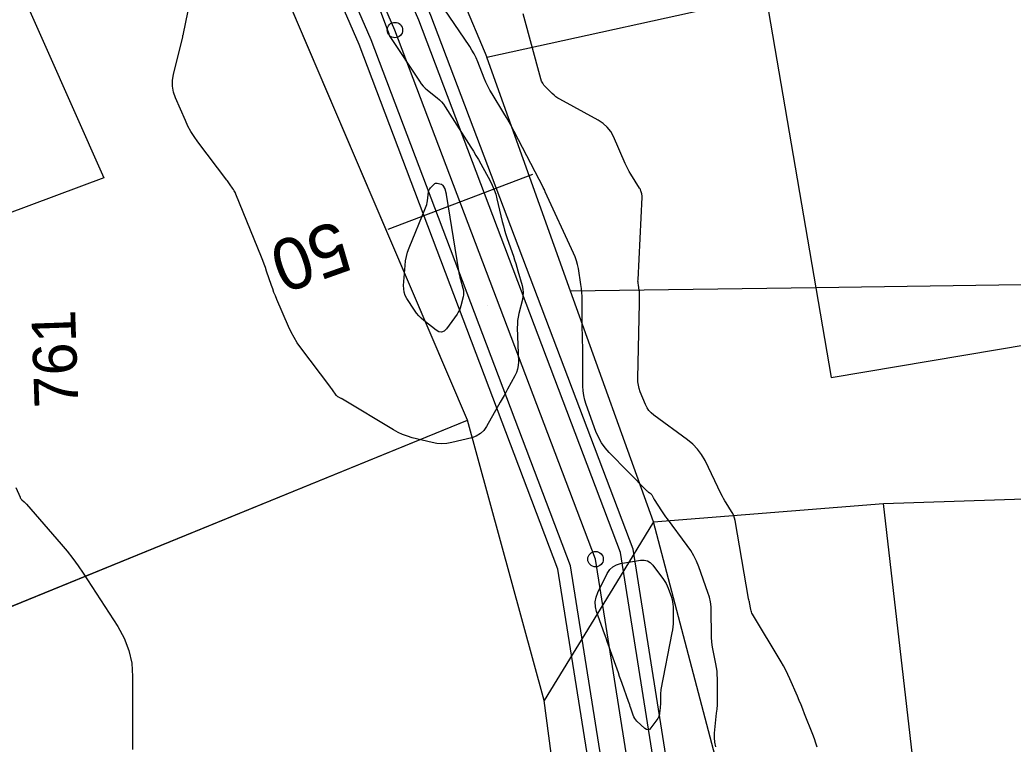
# Model space of a CAD drawing. Extents: x -534481 to -534262, y -1190577 to -1190138.
# Drawn here: x -534403.93 to -534384.66, y -1190491.61 to -1190477.55 of the extents above; entities that cross this region are included whole.
import ezdxf

# ---------------------------------------------------------------- set-up
doc = ezdxf.new("R2010")
doc.units = 0
for name, color, linetype in [('Bonity', 7, 'Continuous'), ('Definiční body', 7, 'Continuous'), ('Polygon budovy', 7, 'Continuous'), ('Polygon parcely', 7, 'Continuous'), ('Vrstva 18', 7, 'Continuous'), ('Vrstva 19', 7, 'Continuous'), ('Vrstva 31', 7, 'Continuous'), ('Vrstva 35', 7, 'Continuous'), ('Vrstva 37', 7, 'Continuous')]:
    doc.layers.add(name, color=color, linetype=linetype)

msp = doc.modelspace()

# ---------------------------------------------------------------- linework, layer by layer
at = {"layer": 'Bonity'}
msp.add_lwpolyline([(-534408.105, -1190518.46), (-534393.616, -1190502.389), (-534391.346, -1190496.962), (-534392.763, -1190488.017), (-534396.655, -1190477.752), (-534402.513, -1190464.283), (-534404.757, -1190456.741), (-534408.311, -1190433.088), (-534409.248, -1190427.879), (-534409.316, -1190416.054), (-534409.076, -1190409.418), (-534409.868, -1190391.439)], dxfattribs=at)
at = {"layer": 'Definiční body'}
for p, q in [((-534397.97, -1190470.9), (-534394.87, -1190478.28)), ((-534395.25, -1190485.32), (-534400.89, -1190472.11)), ((-534394.77, -1190478.57), (-534394.87, -1190478.28)), ((-534393.25, -1190482.82), (-534394.77, -1190478.57)), ((-534391.64, -1190487.29), (-534393.25, -1190482.82)), ((-534408.72, -1190490.82), (-534395.25, -1190485.32)), ((-534393.76, -1190490.76), (-534395.25, -1190485.32)), ((-534391.64, -1190487.29), (-534387.18, -1190486.94))]:
    msp.add_line(p, q, dxfattribs=at)
for points in [[(-534394.87, -1190478.28), (-534389.45, -1190477.08), (-534382.56, -1190476.12), (-534376.75, -1190475.31)], [(-534377.4, -1190482.59), (-534388.49, -1190482.75), (-534393.25, -1190482.82)], [(-534387.18, -1190486.94), (-534381.11, -1190486.74), (-534380.38, -1190486.72), (-534376.48, -1190486.28)], [(-534385.13, -1190504.81), (-534385.97, -1190497.46), (-534387.18, -1190486.94)], [(-534391.64, -1190487.29), (-534392.36, -1190488.47), (-534393.76, -1190490.76)], [(-534389.82, -1190497.69), (-534389.73, -1190494.54), (-534391.64, -1190487.29)], [(-534393.4, -1190496.16), (-534393.44, -1190493.16), (-534393.76, -1190490.76)]]:
    msp.add_lwpolyline(points, dxfattribs=at)
at = {"layer": 'Polygon parcely'}
for points in [[(-534413.98, -1190478.05), (-534410.74, -1190485.76), (-534408.96, -1190490.21), (-534408.72, -1190490.82), (-534395.25, -1190485.32), (-534400.89, -1190472.11), (-534405.17, -1190474.16), (-534402.3, -1190480.62), (-534406.62, -1190482.23), (-534409.2, -1190476.06), (-534410.27, -1190476.57)], [(-534389.45, -1190477.08), (-534389.41, -1190477.39), (-534388.49, -1190482.75), (-534388.19, -1190484.49), (-534381.78, -1190483.41), (-534381.11, -1190486.74), (-534380.38, -1190486.72), (-534376.48, -1190486.28), (-534376.96, -1190484.36), (-534377.4, -1190482.59), (-534375.83, -1190482.13), (-534376.75, -1190475.31), (-534382.56, -1190476.12)]]:
    msp.add_lwpolyline(points, close=True, dxfattribs=at)
at = {"layer": 'Vrstva 18'}
for points in [[(-534397.096, -1190476.95), (-534396.777, -1190477.804), (-534396.774, -1190477.81), (-534396.773, -1190477.816), (-534396.771, -1190477.821), (-534396.77, -1190477.828), (-534396.765, -1190477.852), (-534396.763, -1190477.858), (-534396.761, -1190477.863), (-534396.759, -1190477.869), (-534396.756, -1190477.874), (-534396.178, -1190478.746), (-534396.144, -1190478.794), (-534396.106, -1190478.838), (-534396.065, -1190478.88), (-534396.021, -1190478.918), (-534395.836, -1190479.065), (-534395.791, -1190479.104), (-534395.75, -1190479.145), (-534395.713, -1190479.19), (-534395.68, -1190479.239), (-534395.181, -1190480.022), (-534395.132, -1190480.102), (-534395.083, -1190480.183), (-534395.036, -1190480.265), (-534394.99, -1190480.347), (-534394.809, -1190480.679), (-534394.767, -1190480.763), (-534394.73, -1190480.849), (-534394.7, -1190480.938), (-534394.675, -1190481.028), (-534394.572, -1190481.469), (-534394.552, -1190481.552), (-534394.529, -1190481.634), (-534394.504, -1190481.715), (-534394.477, -1190481.796), (-534394.357, -1190482.14), (-534394.333, -1190482.21), (-534394.311, -1190482.28), (-534394.289, -1190482.35), (-534394.269, -1190482.42), (-534394.187, -1190482.71), (-534394.173, -1190482.777), (-534394.167, -1190482.845), (-534394.171, -1190482.912), (-534394.183, -1190482.98), (-534394.251, -1190483.251), (-534394.266, -1190483.319), (-534394.275, -1190483.387), (-534394.28, -1190483.456), (-534394.281, -1190483.526), (-534394.259, -1190484.187), (-534394.262, -1190484.259), (-534394.274, -1190484.328), (-534394.295, -1190484.396), (-534394.326, -1190484.461), (-534394.468, -1190484.717), (-534394.503, -1190484.781), (-534394.539, -1190484.844), (-534394.575, -1190484.908), (-534394.611, -1190484.972), (-534394.876, -1190485.441), (-534394.931, -1190485.52), (-534394.998, -1190485.582), (-534395.076, -1190485.63), (-534395.166, -1190485.661), (-534395.551, -1190485.756), (-534395.647, -1190485.774), (-534395.743, -1190485.78), (-534395.839, -1190485.774), (-534395.935, -1190485.756), (-534396.319, -1190485.66), (-534396.414, -1190485.633), (-534396.506, -1190485.599), (-534396.594, -1190485.558), (-534396.681, -1190485.51), (-534397.67, -1190484.912), (-534397.677, -1190484.908), (-534397.684, -1190484.904), (-534397.691, -1190484.901), (-534397.699, -1190484.897), (-534397.738, -1190484.88), (-534397.746, -1190484.876), (-534397.759, -1190484.869), (-534397.764, -1190484.865), (-534397.769, -1190484.862), (-534397.784, -1190484.85), (-534397.787, -1190484.847), (-534397.789, -1190484.844), (-534397.792, -1190484.841), (-534397.795, -1190484.838), (-534397.866, -1190484.734), (-534397.878, -1190484.715), (-534397.891, -1190484.697), (-534397.905, -1190484.679), (-534397.918, -1190484.661), (-534398.48, -1190483.918), (-534398.549, -1190483.82), (-534398.612, -1190483.719), (-534398.669, -1190483.614), (-534398.72, -1190483.506), (-534398.946, -1190482.979), (-534398.974, -1190482.911), (-534399.001, -1190482.843), (-534399.026, -1190482.775), (-534399.05, -1190482.706), (-534399.143, -1190482.429), (-534399.167, -1190482.36), (-534399.191, -1190482.291), (-534399.217, -1190482.223), (-534399.244, -1190482.155), (-534399.738, -1190480.933), (-534399.741, -1190480.927), (-534399.744, -1190480.921), (-534399.747, -1190480.915), (-534399.75, -1190480.909), (-534399.774, -1190480.87), (-534399.787, -1190480.848), (-534399.794, -1190480.838), (-534399.865, -1190480.734), (-534399.878, -1190480.716), (-534399.89, -1190480.698), (-534399.904, -1190480.68), (-534399.917, -1190480.662), (-534400.48, -1190479.918), (-534400.549, -1190479.82), (-534400.612, -1190479.719), (-534400.669, -1190479.614), (-534400.72, -1190479.506), (-534400.909, -1190479.065), (-534400.947, -1190478.954), (-534400.966, -1190478.841), (-534400.966, -1190478.727), (-534400.947, -1190478.611), (-534400.771, -1190477.88), (-534400.769, -1190477.87), (-534400.766, -1190477.86), (-534400.76, -1190477.841), (-534400.757, -1190477.831), (-534400.755, -1190477.821), (-534400.589, -1190476.994)], [(-534388.464, -1190491.668), (-534388.488, -1190491.585), (-534388.515, -1190491.502), (-534388.546, -1190491.421), (-534388.708, -1190491.015), (-534388.742, -1190490.93), (-534388.777, -1190490.845), (-534388.813, -1190490.76), (-534388.849, -1190490.675), (-534388.994, -1190490.337), (-534389.031, -1190490.253), (-534389.072, -1190490.17), (-534389.115, -1190490.089), (-534389.161, -1190490.01), (-534389.717, -1190489.087), (-534389.729, -1190489.065), (-534389.739, -1190489.042), (-534389.746, -1190489.018), (-534389.751, -1190488.994), (-534389.774, -1190488.858), (-534389.776, -1190488.851), (-534389.777, -1190488.845), (-534389.779, -1190488.838), (-534389.781, -1190488.831), (-534389.791, -1190488.805), (-534389.793, -1190488.799), (-534389.795, -1190488.792), (-534389.796, -1190488.786), (-534389.798, -1190488.779), (-534390.054, -1190487.268), (-534390.065, -1190487.221), (-534390.08, -1190487.176), (-534390.1, -1190487.132), (-534390.124, -1190487.09), (-534390.23, -1190486.926), (-534390.256, -1190486.885), (-534390.281, -1190486.843), (-534390.304, -1190486.8), (-534390.326, -1190486.757), (-534390.64, -1190486.106), (-534390.706, -1190485.989), (-534390.784, -1190485.882), (-534390.876, -1190485.785), (-534390.98, -1190485.699), (-534391.634, -1190485.223), (-534391.685, -1190485.18), (-534391.728, -1190485.132), (-534391.765, -1190485.078), (-534391.794, -1190485.018), (-534391.895, -1190484.768), (-534391.917, -1190484.704), (-534391.932, -1190484.64), (-534391.94, -1190484.574), (-534391.942, -1190484.507), (-534391.91, -1190483.052), (-534391.909, -1190483.031), (-534391.909, -1190483.01), (-534391.909, -1190482.99), (-534391.909, -1190482.969), (-534391.909, -1190482.886), (-534391.909, -1190482.865), (-534391.911, -1190482.845), (-534391.913, -1190482.824), (-534391.916, -1190482.804), (-534391.933, -1190482.696), (-534391.937, -1190482.671), (-534391.939, -1190482.646), (-534391.94, -1190482.621), (-534391.939, -1190482.596), (-534391.861, -1190480.991), (-534391.861, -1190480.976), (-534391.862, -1190480.961), (-534391.864, -1190480.947), (-534391.868, -1190480.932), (-534391.884, -1190480.874), (-534391.889, -1190480.859), (-534391.894, -1190480.845), (-534391.901, -1190480.832), (-534391.908, -1190480.819), (-534392.079, -1190480.546), (-534392.109, -1190480.496), (-534392.137, -1190480.445), (-534392.164, -1190480.392), (-534392.188, -1190480.339), (-534392.417, -1190479.82), (-534392.47, -1190479.722), (-534392.536, -1190479.636), (-534392.616, -1190479.562), (-534392.71, -1190479.501), (-534393.456, -1190479.094), (-534393.496, -1190479.071), (-534393.534, -1190479.045), (-534393.569, -1190479.016), (-534393.603, -1190478.985), (-534393.734, -1190478.854), (-534393.764, -1190478.82), (-534393.789, -1190478.783), (-534393.809, -1190478.743), (-534393.823, -1190478.7), (-534394.17, -1190477.437)]]:
    msp.add_lwpolyline(points, dxfattribs=at)
msp.add_lwpolyline([(-534391.717, -1190491.319), (-534391.746, -1190491.331), (-534391.777, -1190491.325), (-534391.81, -1190491.302), (-534391.96, -1190491.161), (-534391.984, -1190491.135), (-534392.004, -1190491.108), (-534392.02, -1190491.078), (-534392.033, -1190491.045), (-534392.078, -1190490.911), (-534392.089, -1190490.878), (-534392.1, -1190490.845), (-534392.112, -1190490.811), (-534392.123, -1190490.778), (-534392.247, -1190490.43), (-534392.271, -1190490.361), (-534392.296, -1190490.292), (-534392.32, -1190490.223), (-534392.345, -1190490.154), (-534392.472, -1190489.797), (-534392.502, -1190489.715), (-534392.531, -1190489.633), (-534392.56, -1190489.55), (-534392.589, -1190489.467), (-534392.742, -1190489.032), (-534392.765, -1190488.939), (-534392.769, -1190488.847), (-534392.754, -1190488.756), (-534392.719, -1190488.666), (-534392.536, -1190488.294), (-534392.489, -1190488.221), (-534392.431, -1190488.165), (-534392.36, -1190488.126), (-534392.277, -1190488.103), (-534391.889, -1190488.038), (-534391.82, -1190488.035), (-534391.757, -1190488.05), (-534391.702, -1190488.082), (-534391.654, -1190488.133), (-534391.444, -1190488.413), (-534391.417, -1190488.451), (-534391.393, -1190488.492), (-534391.373, -1190488.534), (-534391.355, -1190488.577), (-534391.292, -1190488.755), (-534391.278, -1190488.8), (-534391.268, -1190488.846), (-534391.262, -1190488.892), (-534391.26, -1190488.939), (-534391.259, -1190489.208), (-534391.26, -1190489.269), (-534391.264, -1190489.329), (-534391.271, -1190489.389), (-534391.281, -1190489.449), (-534391.494, -1190490.548), (-534391.499, -1190490.577), (-534391.502, -1190490.607), (-534391.504, -1190490.636), (-534391.505, -1190490.666), (-534391.504, -1190490.79), (-534391.504, -1190490.817), (-534391.505, -1190490.844), (-534391.507, -1190490.872), (-534391.509, -1190490.899), (-534391.521, -1190491.007), (-534391.525, -1190491.034), (-534391.533, -1190491.059), (-534391.544, -1190491.083), (-534391.558, -1190491.106), (-534391.69, -1190491.29)], close=True, dxfattribs=at)
at = {"layer": 'Vrstva 19'}
for points in [[(-534390.433, -1190491.658), (-534390.451, -1190491.57), (-534390.457, -1190491.482), (-534390.453, -1190491.391), (-534390.414, -1190491.008), (-534390.406, -1190490.926), (-534390.401, -1190490.844), (-534390.398, -1190490.762), (-534390.398, -1190490.68), (-534390.4, -1190490.333), (-534390.402, -1190490.26), (-534390.407, -1190490.188), (-534390.417, -1190490.116), (-534390.429, -1190490.045), (-534390.487, -1190489.759), (-534390.499, -1190489.688), (-534390.508, -1190489.616), (-534390.514, -1190489.544), (-534390.516, -1190489.471), (-534390.518, -1190489.038), (-534390.522, -1190488.942), (-534390.534, -1190488.847), (-534390.555, -1190488.754), (-534390.583, -1190488.663), (-534390.76, -1190488.167), (-534390.804, -1190488.057), (-534390.856, -1190487.95), (-534390.916, -1190487.848), (-534390.984, -1190487.75), (-534391.37, -1190487.236), (-534391.398, -1190487.198), (-534391.426, -1190487.16), (-534391.452, -1190487.121), (-534391.478, -1190487.082), (-534391.621, -1190486.862), (-534391.626, -1190486.853), (-534391.632, -1190486.844), (-534391.636, -1190486.835), (-534391.641, -1190486.826), (-534391.659, -1190486.788), (-534391.664, -1190486.779), (-534391.67, -1190486.771), (-534391.677, -1190486.764), (-534391.685, -1190486.757), (-534391.724, -1190486.729), (-534391.734, -1190486.722), (-534391.742, -1190486.714), (-534391.751, -1190486.707), (-534391.759, -1190486.699), (-534392.498, -1190485.948), (-534392.579, -1190485.857), (-534392.649, -1190485.758), (-534392.708, -1190485.653), (-534392.755, -1190485.54), (-534392.946, -1190485.017), (-534392.973, -1190484.93), (-534392.993, -1190484.842), (-534393.005, -1190484.752), (-534393.009, -1190484.661), (-534393.009, -1190484.246), (-534393.009, -1190484.178), (-534393.009, -1190484.11), (-534393.01, -1190484.042), (-534393.011, -1190483.974), (-534393.017, -1190483.703), (-534393.019, -1190483.635), (-534393.02, -1190483.567), (-534393.02, -1190483.499), (-534393.02, -1190483.432), (-534393.02, -1190483.002), (-534393.022, -1190482.923), (-534393.027, -1190482.845), (-534393.034, -1190482.767), (-534393.046, -1190482.689), (-534393.097, -1190482.379), (-534393.112, -1190482.302), (-534393.133, -1190482.227), (-534393.158, -1190482.153), (-534393.188, -1190482.081), (-534393.739, -1190480.892), (-534393.743, -1190480.882), (-534393.746, -1190480.873), (-534393.753, -1190480.852), (-534393.756, -1190480.845), (-534393.759, -1190480.838), (-534393.77, -1190480.818), (-534393.773, -1190480.811), (-534394.342, -1190479.717), (-534394.389, -1190479.627), (-534394.438, -1190479.538), (-534394.489, -1190479.45), (-534394.541, -1190479.363), (-534394.77, -1190478.99), (-534394.813, -1190478.916), (-534394.853, -1190478.841), (-534394.889, -1190478.765), (-534394.922, -1190478.686), (-534395.047, -1190478.37), (-534395.081, -1190478.292), (-534395.118, -1190478.216), (-534395.16, -1190478.142), (-534395.205, -1190478.07), (-534395.7, -1190477.339)], [(-534404.007, -1190486.624), (-534403.927, -1190486.816), (-534403.921, -1190486.83), (-534403.913, -1190486.842), (-534403.904, -1190486.854), (-534403.893, -1190486.865), (-534403.847, -1190486.905), (-534403.835, -1190486.915), (-534403.824, -1190486.926), (-534403.814, -1190486.937), (-534403.803, -1190486.948), (-534403.126, -1190487.727), (-534403.012, -1190487.863), (-534402.903, -1190488.002), (-534402.799, -1190488.145), (-534402.7, -1190488.292), (-534402.031, -1190489.324), (-534401.905, -1190489.551), (-534401.815, -1190489.788), (-534401.761, -1190490.036), (-534401.743, -1190490.295), (-534401.743, -1190491.711)]]:
    msp.add_lwpolyline(points, dxfattribs=at)
msp.add_lwpolyline([(-534395.702, -1190483.595), (-534395.75, -1190483.615), (-534395.802, -1190483.609), (-534395.857, -1190483.576), (-534396.094, -1190483.386), (-534396.145, -1190483.342), (-534396.192, -1190483.294), (-534396.235, -1190483.242), (-534396.274, -1190483.187), (-534396.421, -1190482.959), (-534396.453, -1190482.9), (-534396.474, -1190482.839), (-534396.485, -1190482.775), (-534396.486, -1190482.709), (-534396.459, -1190482.317), (-534396.45, -1190482.229), (-534396.433, -1190482.144), (-534396.41, -1190482.06), (-534396.38, -1190481.977), (-534396.061, -1190481.202), (-534396.048, -1190481.168), (-534396.038, -1190481.133), (-534396.029, -1190481.098), (-534396.023, -1190481.062), (-534396.001, -1190480.889), (-534395.996, -1190480.867), (-534395.988, -1190480.848), (-534395.978, -1190480.829), (-534395.964, -1190480.813), (-534395.893, -1190480.741), (-534395.881, -1190480.731), (-534395.868, -1190480.725), (-534395.854, -1190480.722), (-534395.838, -1190480.724), (-534395.761, -1190480.739), (-534395.753, -1190480.741), (-534395.745, -1190480.745), (-534395.739, -1190480.751), (-534395.733, -1190480.758), (-534395.709, -1190480.795), (-534395.704, -1190480.805), (-534395.698, -1190480.815), (-534395.687, -1190480.835), (-534395.685, -1190480.84), (-534395.682, -1190480.845), (-534395.68, -1190480.85), (-534395.679, -1190480.856), (-534395.668, -1190480.905), (-534395.665, -1190480.915), (-534395.663, -1190480.925), (-534395.661, -1190480.935), (-534395.66, -1190480.945), (-534395.42, -1190482.421), (-534395.413, -1190482.464), (-534395.404, -1190482.507), (-534395.394, -1190482.55), (-534395.382, -1190482.592), (-534395.335, -1190482.76), (-534395.326, -1190482.802), (-534395.322, -1190482.845), (-534395.325, -1190482.887), (-534395.332, -1190482.929), (-534395.376, -1190483.103), (-534395.389, -1190483.146), (-534395.405, -1190483.186), (-534395.426, -1190483.225), (-534395.45, -1190483.262), (-534395.657, -1190483.549)], close=True, dxfattribs=at)
at = {"layer": 'Vrstva 31'}
for p, q in [((-534393.987, -1190480.557), (-534396.792, -1190481.62)), ((-534394.864, -1190483.098), (-534394.864, -1190483.098))]:
    msp.add_line(p, q, dxfattribs=at)
at = {"layer": 'Vrstva 35'}
for points in [[(-534405.407, -1190514.348), (-534394.258, -1190501.982), (-534392.12, -1190496.869), (-534393.492, -1190488.211), (-534397.35, -1190478.035), (-534403.219, -1190464.54), (-534405.491, -1190456.905), (-534409.051, -1190433.21), (-534409.998, -1190427.948), (-534410.066, -1190416.042), (-534409.827, -1190409.421), (-534410.645, -1190390.84)], [(-534405.057, -1190514.333), (-534394.044, -1190502.118), (-534391.862, -1190496.9), (-534393.249, -1190488.146), (-534397.118, -1190477.94), (-534402.983, -1190464.455), (-534405.247, -1190456.85), (-534408.804, -1190433.17), (-534409.748, -1190427.925), (-534409.816, -1190416.046), (-534409.577, -1190409.42), (-534410.397, -1190390.795)], [(-534403.656, -1190514.273), (-534393.187, -1190502.661), (-534390.83, -1190497.024), (-534392.278, -1190487.888), (-534396.191, -1190477.563), (-534402.042, -1190464.111), (-534404.268, -1190456.632), (-534407.818, -1190433.007), (-534408.749, -1190427.833), (-534408.816, -1190416.061), (-534408.576, -1190409.416), (-534409.363, -1190391.537)], [(-534403.306, -1190514.257), (-534392.973, -1190502.796), (-534390.572, -1190497.055), (-534392.035, -1190487.824), (-534395.96, -1190477.469), (-534401.807, -1190464.025), (-534404.023, -1190456.578), (-534407.571, -1190432.966), (-534408.499, -1190427.81), (-534408.566, -1190416.065), (-534408.326, -1190409.415), (-534409.111, -1190391.586)]]:
    msp.add_lwpolyline(points, dxfattribs=at)
at = {"layer": 'Vrstva 37'}
for centre in [(-534396.655, -1190477.752), (-534396.655, -1190477.752), (-534396.655, -1190477.752), (-534396.655, -1190477.752), (-534396.655, -1190477.752), (-534396.655, -1190477.752), (-534392.763, -1190488.017), (-534392.763, -1190488.017), (-534392.763, -1190488.017), (-534392.763, -1190488.017), (-534392.763, -1190488.017), (-534392.763, -1190488.017)]:
    msp.add_circle(centre, 0.15, dxfattribs=at)

# ---------------------------------------------------------------- texts
at = {"layer": 'Polygon budovy'}
msp.add_text('761', height=0.85, rotation=92, dxfattribs=at).set_placement((-534402.793, -1190485.067))
at = {"layer": 'Vrstva 31'}
msp.add_text('50', height=1, rotation=199.5335, dxfattribs=at).set_placement((-534397.754, -1190481.43))

doc.saveas('drawing.dxf')
